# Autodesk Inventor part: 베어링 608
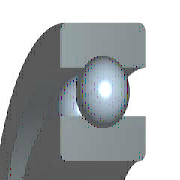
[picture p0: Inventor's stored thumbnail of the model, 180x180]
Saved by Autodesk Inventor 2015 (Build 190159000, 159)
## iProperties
IsCustomPart: 1
Created: 2012-02
Part Number: 베어링 608
Material: 강철, 연강
Description: 깊은 그루브 볼 베어링
Document SubType Name: Modeling
Standard: KS B 2023
Designer: mduedu
Standards Organization: KS
Language: ko-KR
Size Designation: 608 - 8 x 22 x 7
Categories: <MemberInstance><Categories><Category DisplayName="샤프트 부품" InternalName="7f7aeb1f-a693-4053-b835-cee3144e0d98" Mnemonic="SHFT"><Category DisplayName="베어링" Inter
Density: 7.86 g/cm^3
Mass: 12.1605 g
Surface Area: 20.0754 cm^2
Volume: 1.54714 cm^3
Appearance: 노란색
Author: mduedu
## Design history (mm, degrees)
sketch "스케치" dims "d0" = 3.64 (= -0.26 x WD + 0.26 x BD)
  geometry: L1 (1.68, 7.5)-(5.32, 7.5); L2 (3.5, 7.5)-(3.5, 5.68); L3 (3.5, 7.5)-(3.5, 9.32); L4 (2.148, 6.282)-(0, 6.282); L5 (0, 4)-(7, 4); L6 (2.148, 8.718)-(0, 8.718); L7 (0, 11)-(7, 11); L8 (7, 4)-(7, 6.282); L9 (4.852, 6.282)-(7, 6.282); L10 (4.852, 8.718)-(7, 8.718); L11 (7, 11)-(7, 8.718); L12 (-1.4, 0)-(8.4, 0) reference; L13 (0, -0.3)-(0, 5.3) reference
  constraints: 22 end point, 4 point on line, 2 collinear, 2 perpendicular, 2 symmetric about line, 1 midpoint, 1 parallel, 14 other
  dimensions: "d9" = 8 diameter of L5 L12 (= WD); "d11" = 22 diameter of L7 L12 (= BD); "d12" = 7 distance between parallel lines of L8 L13 (= KB); "d13" = 12.564 diameter of L9 L12 (= 0.326 x BD + 0.674 x WD)
revolve "본체" stored, may be unused: angle "d6" = 90 deg
revolve "볼" stored, may be unused: angle "d7" = 90 deg
pattern_circular "IDS_ARRAYBALL[SIMPL:T]" dims angle "d3" = 360 deg
body "Solid1"
fillet "모깎기1" dims "d1" = 0.3 (= KRS)
other parameters: "WD" = 8 [user parameter; used in 5 equation terms], "BD" = 22 [user parameter; used in 5 equation terms], "KB" = 7 [user parameter; used in 1 equation term], "KRS" = 0.3 [user parameter; used in 1 equation term], "d4" = 0, "d5" = 0, "d8" = 0, "d14" = 0, "d15" = 0, "BBA" = 0 [user parameter], "BC0" = 1370000 [user parameter], "BC" = 3250000 [user parameter], "BR" = 11 (= 0.5 x BD) [user parameter], "WR" = 4 (= 0.5 x WD) [user parameter]
